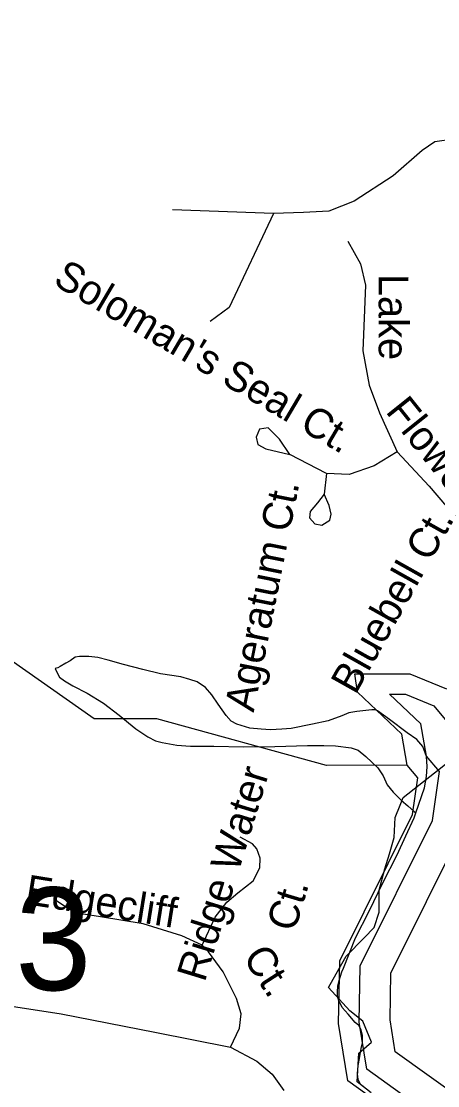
# Model space of a CAD drawing. Extents: x 2001466 to 2224147, y 644118 to 847247.
# Drawn here: x 2059613 to 2060943, y 691316 to 694719 of the extents above; entities that cross this region are included whole.
import ezdxf

# ---------------------------------------------------------------- set-up
doc = ezdxf.new("R2010")
doc.units = 0
for name, color, linetype in [('Exist Boundary Political City Limit New', 7, 'Continuous'), ('Exist Hydrographic Buffer Line', 7, 'Continuous'), ('Exist Hydrographic Creek Single Shore', 7, 'Continuous'), ('Exist Hydrographic Lake Shore', 7, 'Continuous'), ('Exist Hydrographic Misc Water Feature', 7, 'Continuous'), ('Exist Road Non-System Type 51', 7, 'Continuous'), ('Exist Road Non-System Type 51 Label', 7, 'Continuous'), ('Exist Road Secondary Structure Standard Bridge Number Label', 7, 'Continuous'), ('Map Preparation Boundary City Limit Buffer Line', 7, 'Continuous')]:
    doc.layers.add(name, color=color, linetype=linetype)

msp = doc.modelspace()

# ---------------------------------------------------------------- linework, layer by layer
at = {"layer": 'Exist Boundary Political City Limit New'}
msp.add_lwpolyline([(2060730.9, 691293.3), (2060685.8, 691328.7), (2060691.8, 691420.3), (2060731.6, 691454.6), (2060704.2, 691522.4), (2060662.4, 691555.5), (2060594.2, 691629.3), (2060619.2, 691673.4), (2060650.8, 691729.5), (2060709, 691788.9), (2060740.9, 691821.4), (2060756.5, 691870.8), (2060756, 691941.2), (2060775, 692009.4), (2060788.9, 692056.7), (2060803.9, 692109.2), (2060807.9, 692173.4), (2060823.2, 692212.3), (2060833.1, 692237.2), (2061119, 692461.7)], dxfattribs=at)
at = {"layer": 'Exist Hydrographic Buffer Line'}
for points in [[(2060984.2, 691176.2), (2060716.5, 691368.4), (2060692.7, 691519.3), (2060696.2, 691699.4), (2060926.5, 692163.3), (2060949.4, 692320.5), (2060907.6, 692369.8), (2060890, 692472.4), (2060789.6, 692567.3), (2060841, 692567.2), (2060931, 692530), (2061539.9, 691795.7)], [(2061025, 691268.1), (2060807.3, 691424.3), (2060791.3, 691526.1), (2060794.2, 691675.4), (2061021.6, 692133.6), (2061031.7, 692202.9), (2061229.3, 692016.1), (2061480, 691713.8), (2061957.8, 691520.1), (2062156, 691522.1), (2062305.4, 691643.5), (2062466, 691662.4), (2062854.5, 691939.2), (2062865.2, 692099.2), (2062955.3, 692040), (2063068.7, 691965.5), (2063138.4, 691962.3), (2063190.3, 691819.8), (2063184.2, 691551.5), (2063066, 691390.5), (2062774.5, 691197.3)]]:
    msp.add_lwpolyline(points, dxfattribs=at)
at = {"layer": 'Exist Hydrographic Creek Single Shore'}
msp.add_lwpolyline([(2060846, 692341), (2060588.1, 692339.6), (2060046.1, 692488.5), (2059846, 692489.3), (2059537, 692705.5), (2059504, 692788.3), (2059470.1, 692979.2), (2059445.1, 692996.1), (2059319, 693697.5), (2059310, 693904.4), (2059285.2, 693947.6), (2059426, 694430.3), (2059376, 694595.3), (2059375.6, 694719.1)], dxfattribs=at)
at = {"layer": 'Exist Hydrographic Lake Shore'}
msp.add_lwpolyline([(2060957, 691115), (2060655.9, 691331), (2060627, 691514.9), (2060630.9, 691715.4), (2060863, 692183.1), (2060880.2, 692300.7), (2060846, 692341), (2060829, 692439.7), (2060687.1, 692573.9), (2060679.1, 692633.1), (2060854, 692632.8), (2060971.1, 692584.5)], dxfattribs=at)
at = {"layer": 'Exist Hydrographic Misc Water Feature'}
for points in [[(2060745.1, 692518.1), (2060733.2, 692517.9), (2060685.3, 692512.3), (2060659.4, 692508), (2060637.3, 692498.1), (2060593.4, 692482), (2060543.2, 692471.7), (2060475.5, 692457.7), (2060445.4, 692455.8), (2060409.3, 692453.5), (2060379.5, 692455.6), (2060343.6, 692459.4), (2060301.4, 692471.5), (2060283.6, 692481.5), (2060267.4, 692499.4), (2060241.5, 692535.3), (2060221.4, 692565.2), (2060201.5, 692589.2), (2060175.1, 692607), (2060151.1, 692615.1), (2060123, 692623), (2060057.2, 692633), (2060001.2, 692646.8), (2059939.3, 692662.7), (2059890.9, 692676.5), (2059857.1, 692684.5), (2059829.2, 692688.3), (2059799.4, 692688.3), (2059785.1, 692686.4), (2059769.1, 692674.3), (2059754.9, 692666.3), (2059737.1, 692656.4), (2059729.3, 692652.4), (2059721.3, 692650.3)], [(2059721.3, 692650.3), (2059727.5, 692636.4), (2059735.3, 692622.2), (2059751, 692610.5), (2059777.3, 692594.3), (2059823, 692570.4), (2059875.1, 692538.5), (2059925.3, 692500.5), (2059979.3, 692456.6), (2060017.4, 692430.9), (2060041.4, 692418.8), (2060063.3, 692413.1), (2060109.7, 692404.9), (2060153.6, 692401), (2060227.6, 692401.2), (2060323.3, 692399.6), (2060423.2, 692399.9), (2060527.8, 692403.9), (2060579.5, 692403.8), (2060617.4, 692402.1), (2060667.4, 692396.1), (2060689.6, 692388.3), (2060713.4, 692368), (2060751.7, 692332.2), (2060769.5, 692306.4), (2060781.6, 692278.2), (2060801.5, 692254.5), (2060827.8, 692228.2), (2060847.9, 692210.6), (2060867.8, 692192.5), (2060873.9, 692188.4)], [(2060873.9, 692188.4), (2060901.6, 692268.5), (2060907.7, 692304.5), (2060909.6, 692336.7), (2060907.7, 692368.6), (2060895.6, 692400.4), (2060877.2, 692422.7), (2060845.6, 692444.5), (2060789.2, 692486.4), (2060751.5, 692514.4), (2060745.1, 692518.1)], [(2060703.5, 691314.1), (2060695.5, 691322.3), (2060689.8, 691336.1), (2060687.3, 691354.3), (2060689.4, 691380.4), (2060693.1, 691402.5), (2060699.4, 691434.4), (2060703.1, 691452.5), (2060703.3, 691466.3), (2060702.9, 691476.5), (2060699.2, 691494.5), (2060691.2, 691508.3), (2060679.3, 691518.2), (2060657.2, 691544.3), (2060638.7, 691566.1), (2060627, 691590.2), (2060623.1, 691604.2), (2060622.9, 691616), (2060624.8, 691634.4), (2060628.9, 691652), (2060636.9, 691679.9), (2060642.8, 691692), (2060680.5, 691788.2), (2060724.6, 691874.3), (2060768.1, 691964.3), (2060814, 692054.3), (2060841.9, 692114.5), (2060867.8, 692172.6), (2060873.9, 692188.4)]]:
    msp.add_lwpolyline(points, dxfattribs=at)
at = {"layer": 'Exist Road Non-System Type 51'}
for points in [[(2061090.2, 694301.9), (2061031.3, 694330.1), (2060995, 694342.2), (2060934.5, 694334.1), (2060894.2, 694305.9), (2060801.4, 694225.2), (2060676.4, 694144.5), (2060595.7, 694112.2), (2060515.1, 694108.2), (2060418.3, 694104.1)], [(2060418.3, 694104.1), (2060095.7, 694116.2)], [(2060418.3, 694104.1), (2060277.1, 693803.9), (2060216.6, 693759.5)], [(2060656.2, 694016.2), (2060696.5, 693943.5), (2060712.7, 693874.9), (2060704.6, 693665.1), (2060724.8, 693556.1), (2060757, 693467.3), (2060813.5, 693342.2)], [(2060587.7, 693273.6), (2060470.7, 693334.2), (2060438.4, 693382.6), (2060402.2, 693418.9), (2060373.9, 693414.9), (2060363.1, 693389.4), (2060369, 693365.6), (2060394.8, 693351.7), (2060470.7, 693334.2)], [(2060813.5, 693342.2), (2060740.9, 693297.8), (2060660.3, 693269.6), (2060587.7, 693273.6)], [(2060813.5, 693342.2), (2060915.9, 693232.8), (2060971.3, 693167.4), (2061020.9, 693125.7), (2061038.7, 693111.9)], [(2060587.7, 693273.6), (2060581, 693207), (2060559.2, 693179.3), (2060535.5, 693151.5), (2060533.5, 693131.7), (2060551.3, 693111.9), (2060573.1, 693107.9), (2060598.9, 693123.8), (2060602.8, 693143.6), (2060596.9, 693171.3), (2060581, 693207)], [(2060190.9, 691765.4), (2060232.3, 691855), (2060269.7, 691903.1), (2060304.5, 691932.5), (2060353.9, 691971.3), (2060375.3, 692012.7), (2060376.6, 692043.5), (2060366, 692072.9), (2060351.3, 692089), (2060312.5, 692110.4)], [(2060190.9, 691765.4), (2060125.4, 691794.8), (2060002.5, 691833.6), (2059866.1, 691856.3), (2059804.7, 691865.7), (2059767.3, 691879), (2059720.5, 691909.8)], [(2060281.8, 691439.1), (2060309.8, 691499.3), (2060315.2, 691546.1), (2060300.5, 691594.2), (2060257.7, 691679.8), (2060210.9, 691744), (2060190.9, 691765.4)], [(2058498.5, 691449.5), (2058634.3, 691489.9), (2058745.2, 691523.3), (2058960.3, 691574.2), (2059132.7, 691586.2), (2059306.5, 691591.5), (2059538.7, 691576.8), (2059740.5, 691546.1), (2060039.9, 691487.2), (2060281.8, 691439.1)], [(2060281.8, 691439.1), (2060366, 691393.9), (2060414.1, 691352.5), (2060451.5, 691300.3)]]:
    msp.add_lwpolyline(points, dxfattribs=at)
at = {"layer": 'Map Preparation Boundary City Limit Buffer Line'}
msp.add_lwpolyline([(2060730.9, 691293.3), (2060685.8, 691328.7), (2060691.8, 691420.3), (2060731.6, 691454.6), (2060704.2, 691522.4), (2060662.4, 691555.5), (2060594.2, 691629.3), (2060619.2, 691673.4), (2060650.8, 691729.5), (2060709, 691788.9), (2060740.9, 691821.4), (2060756.5, 691870.8), (2060756, 691941.2), (2060775, 692009.4), (2060788.9, 692056.7), (2060803.9, 692109.2), (2060807.9, 692173.4), (2060823.2, 692212.3), (2060833.1, 692237.2), (2061119, 692461.7)], dxfattribs=at)

# ---------------------------------------------------------------- texts
at = {"layer": 'Exist Road Non-System Type 51 Label'}
for s, rotation, p in [("Soloman's Seal Ct.", 329.5026, (2059710.5, 693880.1)), ('Lake', 270.0751, (2060754.6, 693911.3)), ('Flower', 308.6244, (2060774.4, 693471.1)), ('Ageratum Ct.', 78.704, (2060355.3, 692507.5)), ('Bluebell Ct.', 60.6731, (2060680.3, 692562.7)), ('Ridge Water', 72.9365, (2060198.9, 691644.2)), ('Edgecliff', 350.8661, (2059621.2, 691897.3)), ('Ct.', 73.323, (2060486.2, 691804.4)), ('Ct.', 302.8943, (2060318.7, 691726.6))]:
    msp.add_text(s, height=95, rotation=rotation, dxfattribs=at).set_placement(p)
at = {"layer": 'Exist Road Secondary Structure Standard Bridge Number Label'}
msp.add_text('373', height=328.08, dxfattribs=at).set_placement((2059105.4, 691621.4))

doc.saveas('drawing.dxf')
